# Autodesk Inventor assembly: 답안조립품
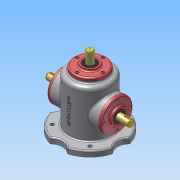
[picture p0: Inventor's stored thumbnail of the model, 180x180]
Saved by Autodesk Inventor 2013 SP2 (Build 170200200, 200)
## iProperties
Created: 2026-07
Part Number: 답안조립품
Document SubType Name: Assembly
Designer: 601
Author: 601
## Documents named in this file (12)
- C:\Users\601\Desktop\760703V1004\답안조립품.iam
- C:\Users\601\Desktop\760703V1004\본체.ipt
- C:\Users\601\Desktop\760703V1004\커버.ipt
- C:\Users\601\Desktop\760703V1004\6각 구멍붙이 볼트 M4x10.ipt
- C:\Users\601\Desktop\760703V1004\오일 실 17 32 8.ipt
- C:\Users\601\Desktop\760703V1004\깊은 홈 볼 베어링 6203.ipt
- C:\Users\601\Desktop\760703V1004\메인 축.ipt
- C:\Users\601\Desktop\760703V1004\평행 키 5x5x14.ipt
- C:\Users\601\Desktop\760703V1004\메인 베벨기어.ipt
- C:\Users\601\Desktop\760703V1004\서브 축.ipt
- C:\Users\601\Desktop\760703V1004\평행 키 4x4x14.ipt
- C:\Users\601\Desktop\760703V1004\서브 베벨기어.ipt
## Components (12 placed, 1 different names)
1. 6각 구멍붙이 볼트 M4x10:1 — 각도:1
2. 6각 구멍붙이 볼트 M4x10:2
3. 6각 구멍붙이 볼트 M4x10:3
4. 6각 구멍붙이 볼트 M4x10:4
5. 6각 구멍붙이 볼트 M4x10:5 — 각도:4
6. 6각 구멍붙이 볼트 M4x10:6
7. 6각 구멍붙이 볼트 M4x10:7
8. 6각 구멍붙이 볼트 M4x10:8
9. 6각 구멍붙이 볼트 M4x10:9 — 각도:7
10. 6각 구멍붙이 볼트 M4x10:10
11. 6각 구멍붙이 볼트 M4x10:11
12. 6각 구멍붙이 볼트 M4x10:12
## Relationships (3: Angle 3)
- 각도:1 [Angle]: 6각 구멍붙이 볼트 M4x10:1
- 각도:4 [Angle]: 6각 구멍붙이 볼트 M4x10:5
- 각도:7 [Angle]: 6각 구멍붙이 볼트 M4x10:9
